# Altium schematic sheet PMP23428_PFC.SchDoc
size 431 x 279 mm; Date: Not shown in title block; ApprovedBy: Not shown in title block; CheckedBy: Not shown in title block; Author: Not shown in title block; CompanyName: Not shown in title block; Engineer: Not shown in title block; Organization: Not shown in title block; Address1: Not shown in title block; Address2: Not shown in title block; Address3: Not shown in title block; Address4: Not shown in title block; DocumentNumber: 1; Revision: Use project parameter SCH_Rev; SheetNumber: 1; SheetTotal: 4; PageSetup: Record=PageOptions¦CenterHorizontal=True¦CenterVertical=True¦PrintScale=1.00¦XCorrection=1.00¦YCorrection=1.00¦PrintKind=0¦BorderSize=5000000¦LeftOffset=0¦BottomOffset=0¦Orientation=2¦PaperLength=1000¦PaperWidth=1000¦Scale=100¦PaperSource=15¦PrintQuality=600¦MediaType=1¦DitherType=10¦PaperKind=Letter¦PrintScaleMode=1
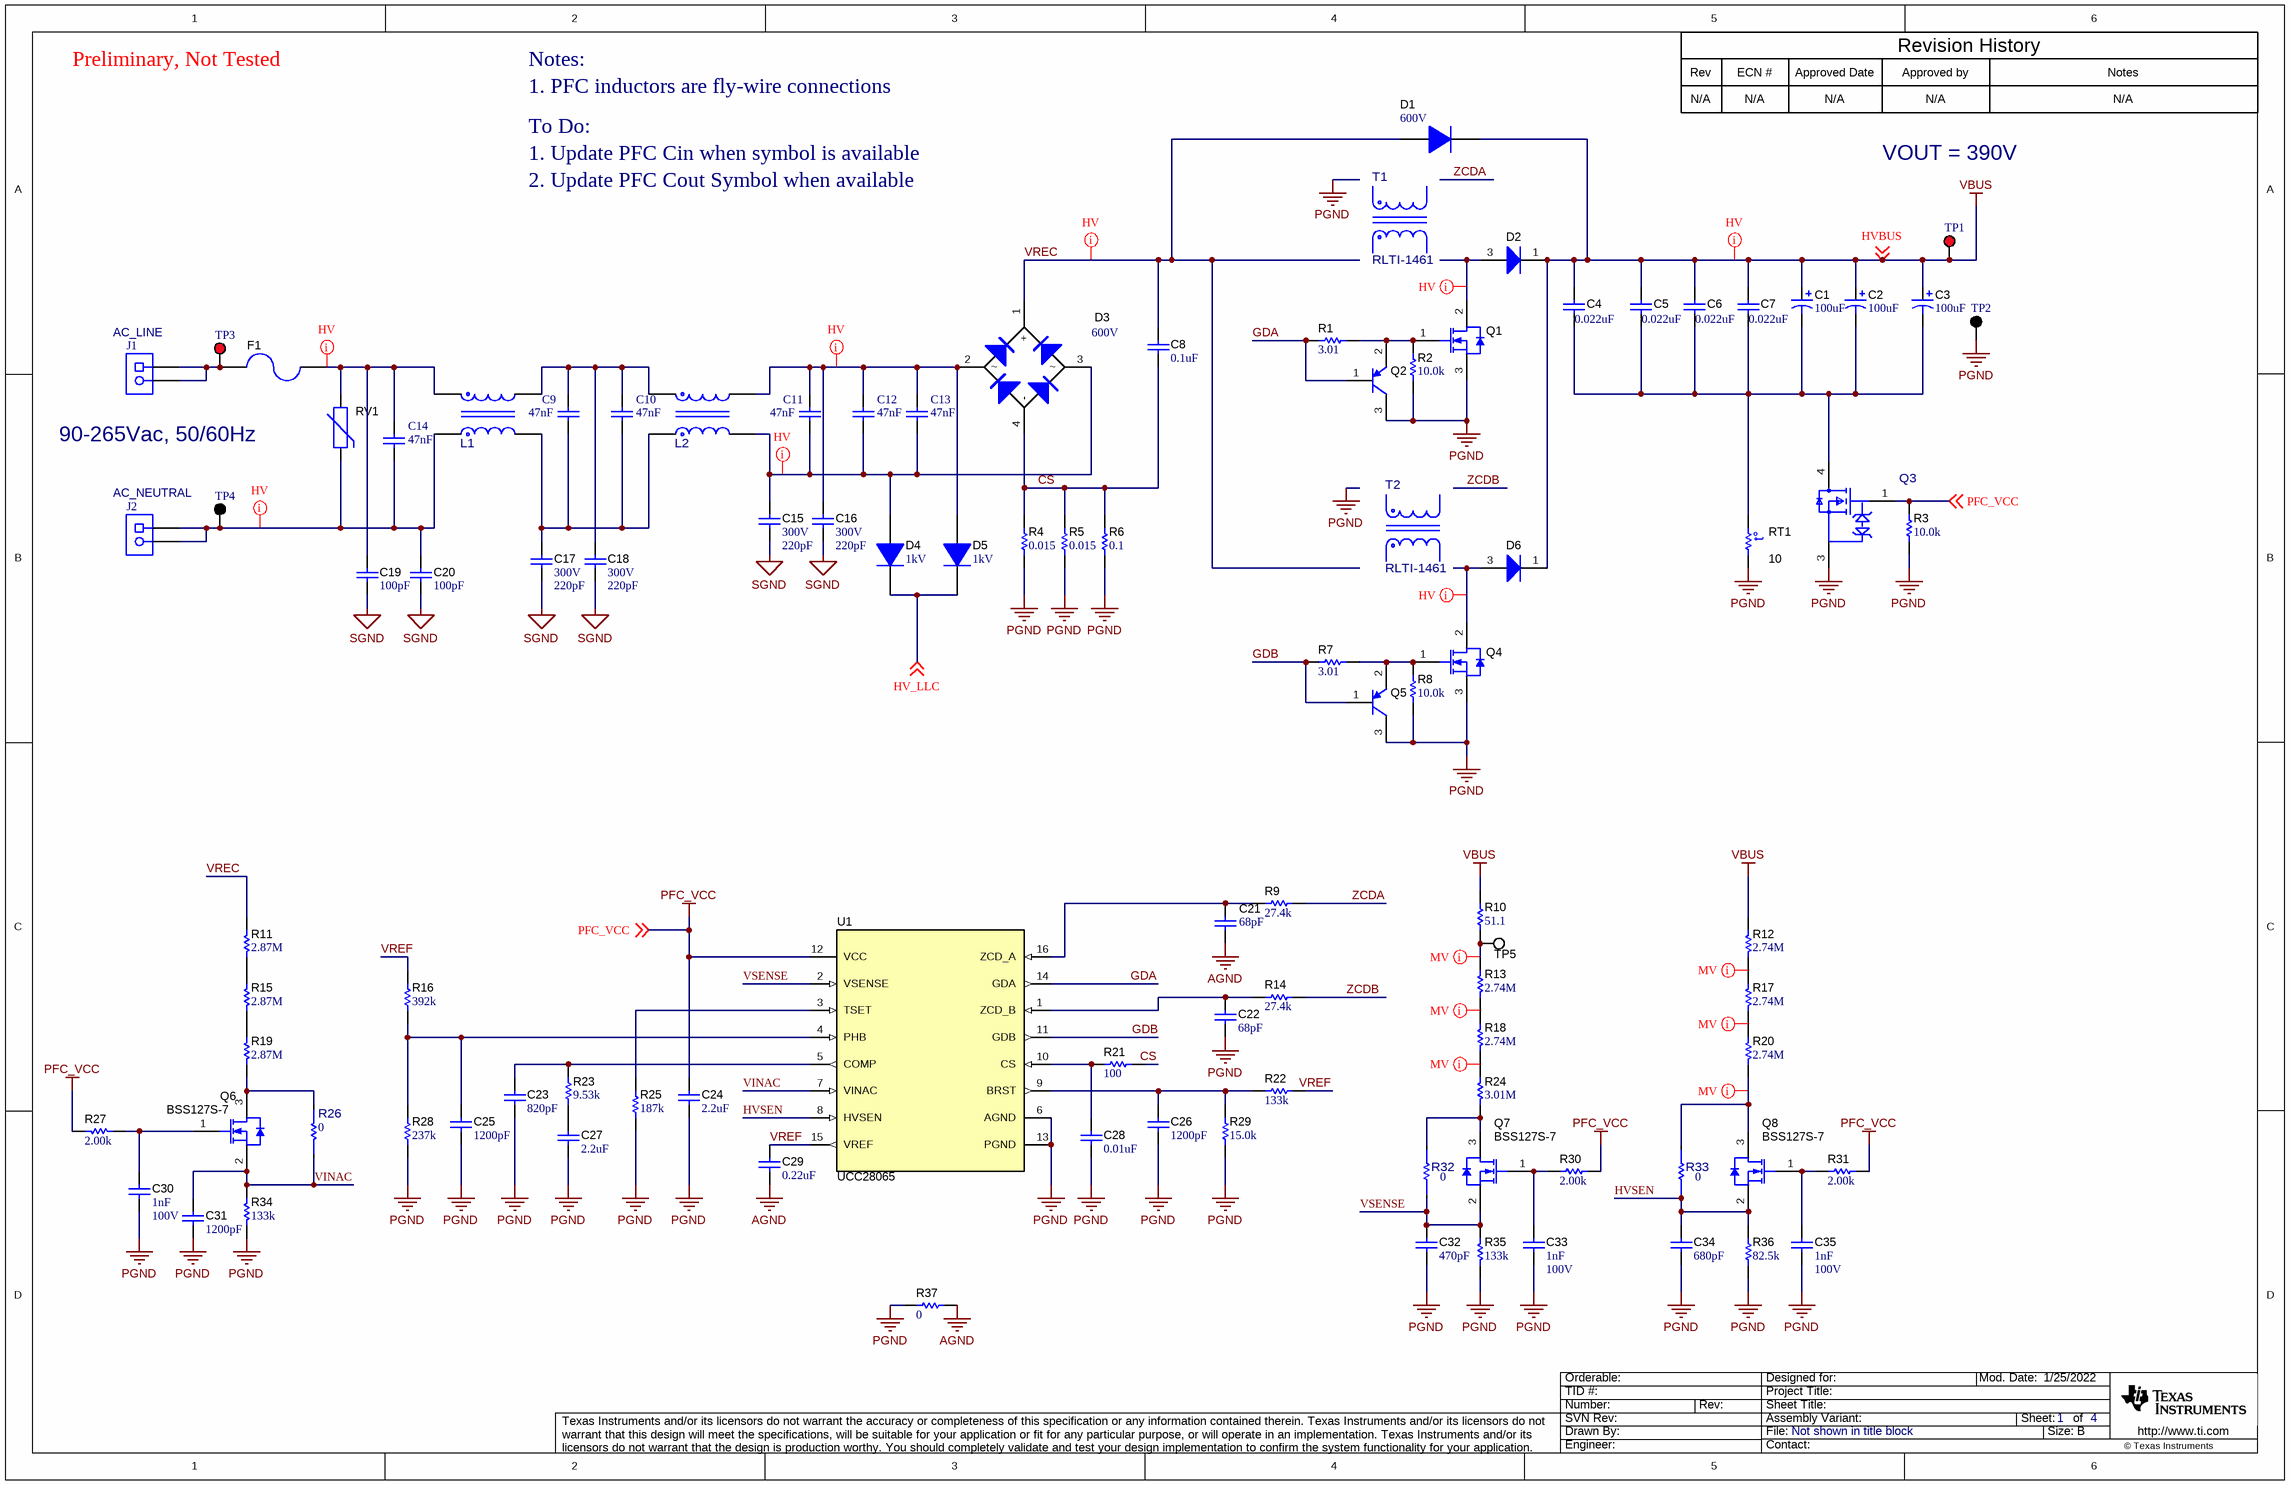
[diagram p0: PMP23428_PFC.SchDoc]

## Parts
C1  ValueDisplayed: 100uF  [KXG_1800x4000_horizontalUp]  (hidden comment: Cap_Polarized)
C2  ValueDisplayed: 100uF  [KXG_1800x4000_horizontalUp]  (hidden comment: Cap_Polarized)
C3  ValueDisplayed: 100uF  [KXG_1800x4000_horizontalDown]  (hidden comment: Cap_Polarized)
C4  ValueDisplayed: 0.022uF  [1210_150]  (hidden comment: GRM32QR72J223KW01L)
C5  ValueDisplayed: 0.022uF  [1210_150]  (hidden comment: GRM32QR72J223KW01L)
C6  ValueDisplayed: 0.022uF  [1210_150]  (hidden comment: GRM32QR72J223KW01L)
C7  ValueDisplayed: 0.022uF  [1210_150]  (hidden comment: GRM32QR72J223KW01L)
C8  ValueDisplayed: 0.1uF  [CAPRR1500W60L1750T550H1250]  (hidden comment: Capacitor)
C9  Cap_F: 47nF  [WCAP-FTX2_L13W4.5H9.5]  (hidden comment: 890324023015)
C10  Cap_F: 47nF  [WCAP-FTX2_L13W4.5H9.5]  (hidden comment: 890324023015)
C11  Cap_F: 47nF  [WCAP-FTX2_L13W4.5H9.5]  (hidden comment: 890324023015)
C12  Cap_F: 47nF  [WCAP-FTX2_L13W4.5H9.5]  (hidden comment: 890324023015)
C13  Cap_F: 47nF  [WCAP-FTX2_L13W4.5H9.5]  (hidden comment: 890324023015)
C14  Cap_F: 47nF  [WCAP-FTX2_L13W4.5H9.5]  (hidden comment: 890324023015)
C15  VDC_V: 300V  ValueDisplayed: 220pF  [B_800x700x800]  (hidden comment: DE6B3KJ221KN3A)
C16  VDC_V: 300V  ValueDisplayed: 220pF  [B_800x700x800]  (hidden comment: DE6B3KJ221KN3A)
C17  VDC_V: 300V  ValueDisplayed: 220pF  [B_800x700x800]  (hidden comment: DE6B3KJ221KN3A)
C18  VDC_V: 300V  ValueDisplayed: 220pF  [B_800x700x800]  (hidden comment: DE6B3KJ221KN3A)
C19  ValueDisplayed: 100pF  [KY_700x500x1000]  (hidden comment: DE2B3KY101KN3AU02F)
C20  ValueDisplayed: 100pF  [KY_700x500x1000]  (hidden comment: DE2B3KY101KN3AU02F)
C21  ValueDisplayed: 68pF  [0805_HV]  (hidden comment: Capacitor)
C22  ValueDisplayed: 68pF  [0805_HV]  (hidden comment: Capacitor)
C23  ValueDisplayed: 820pF  [0805_HV]  (hidden comment: Capacitor)
C24  ValueDisplayed: 2.2uF  [0805_HV]  (hidden comment: Capacitor)
C25  ValueDisplayed: 1200pF  [0805_HV]  (hidden comment: Capacitor)
C26  ValueDisplayed: 1200pF  [0805_HV]  (hidden comment: Capacitor)
C27  ValueDisplayed: 2.2uF  [0805_HV]  (hidden comment: Capacitor)
C28  ValueDisplayed: 0.01uF  [0805_HV]  (hidden comment: Capacitor)
C29  ValueDisplayed: 0.22uF  [1206]  (hidden comment: Capacitor)
C30  Cap_F: 1nF  VDC_V: 100V  [0603]  (hidden comment: C1608X7R2A102K080AA)
C31  ValueDisplayed: 1200pF  [0805_HV]  (hidden comment: Capacitor)
C32  ValueDisplayed: 470pF  [0805_HV]  (hidden comment: Capacitor)
C33  Cap_F: 1nF  VDC_V: 100V  [0603]  (hidden comment: C1608X7R2A102K080AA)
C34  ValueDisplayed: 680pF  [0805_HV]  (hidden comment: Capacitor)
C35  Cap_F: 1nF  VDC_V: 100V  [0603]  (hidden comment: C1608X7R2A102K080AA)
D1  Vr_V: 600V  [SMC]  (hidden comment: DIODE)
D2  MUR860G  [TO-220AC_HORIZ]  (value not drawn)
D3  Vr_V: 600V  [GBU_Horizontal_Down_Standoff2300]  (hidden comment: GBU6J)
D4  Vr_V: 1kV  [DO-41]  (hidden comment: 1N4007-E3/73)
D5  Vr_V: 1kV  [DO-41]  (hidden comment: 1N4007-E3/73)
D6  MUR860G  [TO-220AC_HORIZ]  (value not drawn)
F1  0216008.MXEP  [FUSE_0216]  (value not drawn)
J1  Receptacle_2x1  [On-Shore_ED120_2DS]  (value not drawn)
J2  Receptacle_2x1  [On-Shore_ED120_2DS]  (value not drawn)
L1  7448680120  [FP-7448680120_PTH_CMC_27MM5_25MM0-MFG]  (value not drawn)
L2  7448680120  [FP-7448680120_PTH_CMC_27MM5_25MM0-MFG]  (value not drawn)
Q1  IPP60R099CPXKSA1  [TO-220AB_Horizontal_100mil_Standoff2300]  (value not drawn)
Q2  FMMT718TA  [SOT-23]  (value not drawn)
Q3  STB18N60DM2  [FP-STB18N60DM2_D2PAK-MFG]  (value not drawn)
Q4  IPP60R099CPXKSA1  [TO-220AB_Horizontal_100mil_Standoff2300]  (value not drawn)
Q5  FMMT718TA  [SOT-23]  (value not drawn)
Q6  BSS127S-7  [SOT-23]
Q7  BSS127S-7  [SOT-23]
Q8  BSS127S-7  [SOT-23]
R1  ValueDisplayed: 3.01  [0603]  (hidden comment: RC0603FR-073R01L)
R2  ValueDisplayed: 10.0k  [0805_HV]  (hidden comment: Resistor)
R3  ValueDisplayed: 10.0k  [0805_HV]  (hidden comment: Resistor)
R4  ValueDisplayed: 0.015  [2010]  (hidden comment: Resistor)
R5  ValueDisplayed: 0.015  [2010]  (hidden comment: Resistor)
R6  ValueDisplayed: 0.1  [2010]  (hidden comment: CRM2010-FX-R100ELF)
R7  ValueDisplayed: 3.01  [0603]  (hidden comment: RC0603FR-073R01L)
R8  ValueDisplayed: 10.0k  [0805_HV]  (hidden comment: Resistor)
R9  ValueDisplayed: 27.4k  [0603]  (hidden comment: RC0603FR-0727K4L)
R10  ValueDisplayed: 51.1  [0805_HV]  (hidden comment: Resistor)
R11  ValueDisplayed: 2.87M  [0805_HV]  (hidden comment: Resistor)
R12  ValueDisplayed: 2.74M  [0805_HV]  (hidden comment: Resistor)
R13  ValueDisplayed: 2.74M  [0805_HV]  (hidden comment: Resistor)
R14  ValueDisplayed: 27.4k  [0603]  (hidden comment: RC0603FR-0727K4L)
R15  ValueDisplayed: 2.87M  [0805_HV]  (hidden comment: Resistor)
R16  ValueDisplayed: 392k  [0603]  (hidden comment: RC0603FR-07392KL)
R17  ValueDisplayed: 2.74M  [0805_HV]  (hidden comment: Resistor)
R18  ValueDisplayed: 2.74M  [0805_HV]  (hidden comment: Resistor)
R19  ValueDisplayed: 2.87M  [0805_HV]  (hidden comment: Resistor)
R20  ValueDisplayed: 2.74M  [0805_HV]  (hidden comment: Resistor)
R21  ValueDisplayed: 100  [0805_HV]  (hidden comment: Resistor)
R22  ValueDisplayed: 133k  [0805_HV]  (hidden comment: CRCW0805133KFKEA)
R23  ValueDisplayed: 9.53k  [0805_HV]  (hidden comment: Resistor)
R24  ValueDisplayed: 3.01M  [0805_HV]  (hidden comment: Resistor)
R25  ValueDisplayed: 187k  [0603]  (hidden comment: CRCW0603187KFKEA)
R26  value 0  [FP-RMCF1206ZT0R00_1206-MFG]  (hidden comment: RMCF1206ZT0R00)
R27  ValueDisplayed: 2.00k  [0603]  (hidden comment: RC0603FR-072KL)
R28  ValueDisplayed: 237k  [0603]  (hidden comment: RC0603FR-07237KL)
R29  ValueDisplayed: 15.0k  [0805_HV]  (hidden comment: CRCW080515K0FKEA)
R30  ValueDisplayed: 2.00k  [0603]  (hidden comment: RC0603FR-072KL)
R31  ValueDisplayed: 2.00k  [0603]  (hidden comment: RC0603FR-072KL)
R32  value 0  [FP-RMCF1206ZT0R00_1206-MFG]  (hidden comment: RMCF1206ZT0R00)
R33  value 0  [FP-RMCF1206ZT0R00_1206-MFG]  (hidden comment: RMCF1206ZT0R00)
R34  ValueDisplayed: 133k  [0805_HV]  (hidden comment: CRCW0805133KFKEA)
R35  ValueDisplayed: 133k  [0805_HV]  (hidden comment: Resistor)
R36  ValueDisplayed: 82.5k  [0805_HV]  (hidden comment: Resistor)
R37  ValueDisplayed: 0  [2512]  (hidden comment: Resistor)
RT1  value 10  [S153]  (hidden comment: B57153S0100M000)
RV1  Varistor_MetalOxide  [VAR_S10K275E2]  (value not drawn)
T1  RLTI-1461  [FP-RLTI-1461_PFC_IND_1IN25_3IN0-MFG]
T2  RLTI-1461  [FP-RLTI-1461_PFC_IND_1IN25_3IN0-MFG]
TP1  5010  [Keystone5010]  (value not drawn)
TP2  5011  [Keystone5011]  (value not drawn)
TP3  5010  [Keystone5010]  (value not drawn)
TP4  5011  [Keystone5011]  (value not drawn)
TP5  5002  [Keystone5002]  (value not drawn)
U1  UCC28065  [D0016A_N]

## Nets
AGND: C21.2 C29.2 R37.1
PFC_VCC: C24.2 Q3.1(G) R3.2 R27.2 R30.2 R31.2 U1.12(VCC) ; off-sheet PFC_VCC
PGND: C22.1 C23.1 C24.1 C25.2 C26.2 C27.2 C28.2 C30.2 C31.1 C32.2 C33.2 C34.2 C35.2 Q1.3(S) Q2.3(C) Q3.3(S) Q4.3(S) Q5.3(C) R2.1 R3.1 R4.1 R5.1 R6.1 R8.1 R25.1 R28.1 R29.1 R34.1 R35.1 R36.1 R37.2 RT1.1 TP2.1 U1.6(AGND) U1.13(PGND)
SGND: C15.2 C16.2 C17.2 C18.2 C19.2 C20.2
VBUS: C1.1(+) C2.1(+) C3.1(+) C4.1 C5.1 C6.1 C7.1 D1.1(K) D2.1(K) D6.1(K) R10.2 R12.2 TP1.1 ; off-sheet HVBUS  [also labelled HVBUS]
CS: C8.2 D3.4(-) R4.2 R5.2 R6.2 R21.2
GDA: Q2.1(B) R1.1 U1.14(GDA)
GDB: Q5.1(B) R7.1 U1.11(GDB)
HV_LLC: D4.1(K) D5.1(K) ; off-sheet HV_LLC
HVSEN: C34.1 Q8.2(S) R33.1 R36.2 U1.8(HVSEN)
VINAC: C31.2 Q6.2(S) R26.1 R34.2 U1.7(VINAC)
VREC: C8.1 D1.2(A) D3.1(+) R11.1
VREF: C29.1 R16.2 R22.2 U1.15(VREF)
VSENSE: C32.1 Q7.2(S) R32.1 R35.2 U1.2(VSENSE)
ZCDA: R9.2
ZCDB: R14.2
NetC1_2: C1.2(-) C2.2(-) C3.2(-) C4.2 C5.2 C6.2 C7.2 Q3.4(D) RT1.2
NetC9_1: C9.1 C10.1 C17.1 L1.2 L2.1
NetC9_2: C9.2 C10.2 C18.1 L1.3 L2.4
NetC11_1: C11.1 C12.1 C13.1 C15.1 D3.3 D4.2(A) L2.2
NetC11_2: C11.2 C12.2 C13.2 C16.1 D3.2 D5.2(A) L2.3
NetC14_1: C14.1 C20.1 J2.1 J2.2 L1.1 RV1.2 TP4.1
NetC14_2: C14.2 C19.1 F1.1 L1.4 RV1.1
NetC21_1: C21.1 R9.1 U1.16(ZCD_A)
NetC22_2: C22.2 R14.1 U1.1(ZCD_B)
NetC23_2: C23.2 R23.2 U1.5(COMP)
NetC25_1: C25.1 R16.1 R28.2 U1.4(PHB)
NetC26_1: C26.1 R22.1 R29.2 U1.9(BRST)
NetC27_1: C27.1 R23.1
NetC28_1: C28.1 R21.1 U1.10(CS)
NetC30_1: C30.1 Q6.1(G) R27.1
NetC33_1: C33.1 Q7.1(G) R30.1
NetC35_1: C35.1 Q8.1(G) R31.1
NetD2_3: D2.3(A) Q1.2(D)
NetD6_3: D6.3(A) Q4.2(D)
NetF1_2: F1.2 J1.1 J1.2 TP3.1
NetQ1_1: Q1.1(G) Q2.2(E) R1.2 R2.2
NetQ4_1: Q4.1(G) Q5.2(E) R7.2 R8.2
NetQ6_3: Q6.3(D) R19.1 R26.2
NetQ7_3: Q7.3(D) R24.2 R32.2
NetQ8_3: Q8.3(D) R20.1 R33.2
NetR10_1: R10.1 R13.1 TP5.1
NetR11_2: R11.2 R15.1
NetR12_1: R12.1 R17.2
NetR13_2: R13.2 R18.1
NetR15_2: R15.2 R19.2
NetR17_1: R17.1 R20.2
NetR18_2: R18.2 R24.1
NetR25_2: R25.2 U1.3(TSET)

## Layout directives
net class HV: NetC11_1, NetC11_2, NetC14_1, NetC14_2, NetD2_3, NetD6_3, VBUS, VREC
net class MV: NetQ8_3, NetR10_1, NetR12_1, NetR13_2, NetR17_1, NetR18_2

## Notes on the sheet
- Preliminary, Not Tested
- Notes:
- 1. PFC inductors are fly-wire connections
- Rev
- N/A
- ECN #
- Approved Date
- Approved by
- Revision History
- Notes
- To Do:
- 1. Update PFC Cin when symbol is available
- VOUT = 390V
- 2. Update PFC Cout Symbol when available
- (near J1) AC_LINE
- 90-265Vac, 50/60Hz
- (near J2) AC_NEUTRAL

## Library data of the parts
C1-C3 = CMP-0010042-2: CAP, AL, 100 uF, 450 V, +/- 20%, TH; PartNumber: EKXG451ELL101MM40S; Manufacturer: Chemi-Con; Polarized: Y; CompType: Capacitor; Value: 100uF; U/M: EA; Cap_F: 100µF; Value1: Unknown; VDC_V: 450V; IRMS_A: 8dA; TaMin_C: -25°C; TaMax_C: 105°C; Cap_Case: 18x40mm; SizeAreaWB_mm2: 400; SizeArea_mm2: 324; SizeX_mm: 18; SizeZ_mm: 41.5; AEC Category: Q200; AEC Qualified: N
C4-C7 = CMP-0009248-2: CAP, CERM, 0.022 uF, 630 V, +/- 10%, X7R, 1210; Manufacturer: MuRata; TaMin_C: -55°C; Polarized: N; SizeAreaWB_mm2: 14.7; Value1: Unknown; U/M: EA; TaMax_C: 125°C; SizeZ_mm: 1.5; SizeX_mm: 3.2; SizeY_mm: 2.5; Cap_Case: 1210; Value2: 630V; SizeArea_mm2: 8; Cap_F: 22nF; AEC Category: Q200
C8 = CMP-0012496-3: CAP, Film, 0.1 uF, 275 V, +/- 20%, TH; PartNumber: ECQ-U2A104ML; Manufacturer: Panasonic; Polarized: N; Value: 0.1uF; Cap_F: 100nF; Value1: Unknown; VDC_V: 275V; TaMin_C: -40°C; TaMax_C: 100°C; Cap_Case: Radial 17.5x5.5x12.5; AEC Category: Q200
C9-C14 = CMP-0112456-1: WCAP-FTX2 Film Capacitor, THT, L13 x W4.5 x H9.5mm, 47nF, 275V; Manufacturer: Wurth Elektronik; Capacitance Tolerance: +/-10%; Dissipation Factor @100kHz: 0.5%; Dissipation Factor @10kHz: 0.1%; Insulation Resistance: 30000MOhm; Pitch: 10mm; Rate of Voltage Rise: 300V/us; Technical Reference: MX2P010473K275ASPB15000
C15-C18 = CMP-0009612-2: CAP, CERM, 220 pF, 300 V, +/- 10%, B, TH, 2- Leads, Body 8x7mm, Pin Spacing 7.5mm; Manufacturer: MuRata; TaMin_C: -40°C; Polarized: N; SizeAreaWB_mm2: 90; Value1: Unknown; U/M: EA; Value: 220pF; TaMax_C: 125°C; SizeZ_mm: 11; SizeX_mm: 8; SizeY_mm: 7; Cap_Case: 8x7x8mm; SizeArea_mm2: 56; AEC Category: Q200
C19 C20 = CMP-0009606-4: CAP, CERM, 100 pF, X1 250 VAC/Y2 300 VAC, +/- 10%, B, TH; Manufacturer: MuRata; TaMin_C: -25°C; Polarized: N; SizeAreaWB_mm2: 66.5; Value1: Unknown; U/M: EA; Value: 100pF; TaMax_C: 85°C; SizeZ_mm: 10; SizeX_mm: 7.5; SizeY_mm: 5; Cap_Case: 7x5x10mm; SizeArea_mm2: 37.5; AEC Category: Q200; AC_Safety: X1Y2; VAC_X: 250V; VAC_Y: 300V
C21 C22 = CMP-0007622-2: CAP, CERM, 68 pF, 50 V, +/- 5%, C0G/NP0, 0805; PartNumber: 08055A680JAT2A; Manufacturer: AVX; Polarized: N; Value: 68pF; U/M: EA; ESR_ohm: 4.5d; Value1: 0.45 ohm; VDC_V: 50V; TaMin_C: -55°C; TaMax_C: 125°C; Cap_Case: 0805; SizeArea_mm2: 2.5; SizeAreaWB_mm2: 6.75; SizeX_mm: 2; SizeY_mm: 1.25; SizeZ_mm: 1.45; AEC Category: Q200
C23 = CMP-0008153-2: CAP, CERM, 820 pF, 25 V, +/- 10%, X7R, 0805; PartNumber: GRM216R71E821KA01D; Manufacturer: MuRata; Polarized: N; Value: 820pF; U/M: EA; Value1: Unknown; VDC_V: 25V; TaMin_C: -55°C; TaMax_C: 125°C; Cap_Case: 0805; SizeArea_mm2: 2.5; SizeAreaWB_mm2: 6.75; SizeX_mm: 2; SizeY_mm: 1.25; SizeZ_mm: 1.45; AEC Category: Q200
C24 C27 = CMP-0007877-2: CAP, CERM, 2.2 uF, 50 V, +/- 10%, X7R, 0805; PartNumber: C2012X7R1H225K125AC; Manufacturer: TDK; Polarized: N; Value: 2.2uF; U/M: EA; Cap_F: 2.2µF; ESR_ohm: 3.66m; Value1: 0.00366 ohm; VDC_V: 50V; IRMS_A: 3.41207A; TaMin_C: -55°C; TaMax_C: 125°C; Cap_Case: 0805; SizeArea_mm2: 2.5; SizeAreaWB_mm2: 6.75; SizeX_mm: 2; SizeY_mm: 1.25; SizeZ_mm: 1.45; AEC Category: Q200
C25 C26 C31 = CMP-0008142-2: CAP, CERM, 1200 pF, 25 V, +/- 10%, X7R, 0805; PartNumber: GRM216R71E122KA01D; Manufacturer: MuRata; Polarized: N; Value: 1200pF; U/M: EA; Cap_F: 1.2nF; Value1: Unknown; VDC_V: 25V; TaMin_C: -55°C; TaMax_C: 125°C; Cap_Case: 0805; SizeArea_mm2: 2.5; SizeAreaWB_mm2: 6.75; SizeX_mm: 2; SizeY_mm: 1.25; SizeZ_mm: 1.45; AEC Category: Q200
C28 = CMP-0007629-2: CAP, CERM, 0.01 uF, 50 V, +/- 5%, X7R, 0805; PartNumber: 08055C103JAT2A; Manufacturer: AVX; Polarized: N; Value: 0.01uF; U/M: EA; Cap_F: 10nF; ESR_ohm: 0.078; Value1: 0.078 ohm; VDC_V: 50V; TaMin_C: -55°C; TaMax_C: 125°C; Cap_Case: 0805; SizeArea_mm2: 2.5; SizeAreaWB_mm2: 6.75; SizeX_mm: 2; SizeY_mm: 1.25; SizeZ_mm: 1.45; AEC Category: Q200
C29 = CMP-0008995-2: CAP, CERM, 0.22 uF, 50 V, +/- 10%, X7R, 1206; PartNumber: GRM31MR71H224KA01L; Manufacturer: MuRata; Polarized: N; Value: 0.22uF; U/M: EA; Cap_F: 220nF; Value1: Unknown; VDC_V: 50V; TaMin_C: -55°C; TaMax_C: 125°C; SizeArea_mm2: 5.12; SizeAreaWB_mm2: 10.92; SizeX_mm: 3.2; SizeY_mm: 1.6; SizeZ_mm: 1.35; AEC Category: Q200
C30 C33 C35 = CMP-0007053-4: CAP, CERM, 1000 pF, 100 V, +/- 10%, X7R, 0603; Manufacturer: TDK; TaMin_C: -55°C; Polarized: N; SizeAreaWB_mm2: 4.68; Value1: Unknown; U/M: EA; Value: 1000pF; TaMax_C: 125°C; SizeZ_mm: 1; SizeX_mm: 1.6; SizeY_mm: 0.8; SizeArea_mm2: 1.28; AEC Category: Q200
C32 = CMP-0008150-2: CAP, CERM, 470 pF, 25 V, +/- 10%, X7R, 0805; PartNumber: GRM216R71E471KA01D; Manufacturer: MuRata; Polarized: N; Value: 470pF; U/M: EA; Value1: Unknown; VDC_V: 25V; TaMin_C: -55°C; TaMax_C: 125°C; Cap_Case: 0805; SizeArea_mm2: 2.5; SizeAreaWB_mm2: 6.75; SizeX_mm: 2; SizeY_mm: 1.25; SizeZ_mm: 1.45; AEC Category: Q200
C34 = CMP-0007693-2: CAP, CERM, 680 pF, 25 V, +/- 10%, X7R, 0805; PartNumber: 885012207059; Manufacturer: Wurth Elektronik; Polarized: N; Value: 680pF; U/M: EA; Value1: Unknown; VDC_V: 25V; TaMin_C: -55°C; TaMax_C: 125°C; Cap_Case: 0805; SizeArea_mm2: 2.5; SizeAreaWB_mm2: 6.75; SizeX_mm: 2; SizeY_mm: 1.25; SizeZ_mm: 1.45; AEC Category: Q200
D1 = CMP-0076905-1: Diode, Ultrafast, 600 V, 3 A, SMC; PartNumber: MURS360T3G; Manufacturer: ON Semiconductor; U/M: EA; Vf_V: 1.25V; Value: 600V; Value1: 3A; TJmax_C: 175°C; RJC_CperW: 11.0; SizeAreaWB_mm2: 83.2686; SizeArea_mm2: 50.5686; SizeX_mm: 8.13; SizeY_mm: 6.22; SizeZ_mm: 2.6; AEC Category: Q101; Green_Lifecycle: Active; Green_REACh: Passed
D2 D6 = CMP-0029037-2: Diode, Ultrafast, 600 V, 8 A, TH; Manufacturer: ON Semiconductor; TJmax_C: 175°C; Green_Lifecycle: Not Set; SizeX_mm: 10.15; SizeAreaWB_mm2: 78.975; RJC_CperW: 4.75; SizeArea_mm2: 45.675; Green_REACh: Incomplete; Vf_V: 980mV; Value2: 0.98V; Io_A: 8A; SizeY_mm: 4.5; AEC Category: Q101; SizeZ_mm: 23; Value: 600V
D3 = CMP-0029269-2: Diode, Switching-Bridge, 600 V, 6 A, TH; Manufacturer: Fairchild Semiconductor; U/M: EA; Vf_V: 1V; Value: 600V; Value1: 6A; TJmax_C: 150°C; RJC_CperW: 3.1; SizeAreaWB_mm2: 130.5915; SizeArea_mm2: 75.6315; SizeX_mm: 22.05; SizeY_mm: 3.43; SizeZ_mm: 21.55; AEC Category: Q101; AEC Qualified: N; Green_Lifecycle: Active; Green_REACh: Passed
D4 D5 = CMP-0029188-2: Diode, P-N, 1000 V, 1 A, TH; Manufacturer: Vishay-Semiconductor; Io_A: 1A; SizeAreaWB_mm2: 43.424; TJmax_C: 150°C; Value: 1000V; SizeZ_mm: 23.4; SizeX_mm: 7.2; SizeY_mm: 2.72; Vf_V: 1.1V; SizeArea_mm2: 19.584; AEC Qualified: N; AEC Category: Q101
F1 = CMP-0079917-1: Fuse, 8 A, 250 VAC, TH; Manufacturer: Littelfuse; VAC_V: 250V; Rtyp_Ohm: 0.0123; MeltingTyp: 64.315; Irating_A: 8A; Interrupt_AC: 1.5kA
J1 J2 = CMP-0074910-1: Terminal Block, 5.08 mm, 2x1, Brass, TH; PartNumber: ED120/2DS; Manufacturer: On-Shore Technology; Pitch_mm: 5.08; Gender: Female; Shrouded: N; Row_Count: 1; Current_A: 15A; Voltage_V: 300V; Cert_CULUS: Y; Green_Lifecycle: Not Set; Green_REACh: Incomplete; CNHeader: False; CT: True
L1 L2 = CMP-0120034-1: 330 µH @ 10 kHz 2 Line Common Mode Choke Through Hole 12A DCR 6mOhm; Manufacturer: Wurth Electronics; DCR_ohm: 6m; Ind_H: 330µH; SizeZ_mm: 10mm; AEC Qualified: No; TaMax_C: +60°C; TaMin_C: -40°C; Test Frequency: 10kHz; Tolerance_%: 40%
Q1 Q4 = CMP-0001172-3: MOSFET, N-CH, 600 V, 31 A, TO-220AB; Alternate Manufacturer: None; Manufacturer: Infineon Technologies; SizeZ_mm: 19.4; ChType: N; Value2: 60 nC; VdsMax_V: 600V; SizeX_mm: 10.2; SizeY_mm: 4.5; Vgs_V: 20V; Value: 600V; SizeArea_mm2: 45.9; AEC Category: Q101; IdsMax_A: 31A; SizeAreaWB_mm2: 79.3; U/M: EA; QgTyp_nC: 60
Q2 Q5 = CMP-0000330-2: Transistor, PNP, 20 V, 1.5 A, SOT-23; Manufacturer: Diodes Inc.; TaMax_C: 150°C; Value2: 6; Value1: 1.5 A; Vcesat1_V: 20V; SizeX_mm: 2.5; SizeY_mm: 3; TaMin_C: -55°C; IcRated_A: 1.5A; CompType: BJT; SizeZ_mm: 1.1; Value: 20 V; SizeArea_mm2: 7.5; NPN: 0; PNP: 1; AEC Category: Q101; SizeAreaWB_mm2: 14; U/M: EA
Q3 = CMP-0084087-1: N-Channel 600V 12A (Tc) 90W (Tc) Surface Mount D2PAK; Manufacturer: STMicroelectronics; Rdson45_ohm: 0.26Ω; Threshold Vgs Max: 5V; Input Capacitace At Vds: 800pF @ 100V; Turn On Delay Time: 13.5ns; AEC Qualified: No; ChMode: False; Symbol Name: SYM-STB18N60DM2; Max Forward Diode Voltage: 1.6V; Vgs_V: 25V; Pulse Drain Current: 48A; Standoff Height: 0.03mm; Reverse Recovery Time: 125ns; Number Of N Channels: 1; Turn Off Delay Time: 9.5ns; QgTyp_nC: 20nC @ 10V; TJmax_C: +150°C; Reverse Recovery Charge: 675nC; Power_W: 110W; SizeZ_mm: 4.83mm; Threshold Vgs Min: 3V
Q6-Q8 = CMP-0001149-3: MOSFET, N-CH, 600 V, 0.05 A, SOT-23; Alternate Manufacturer: None; Manufacturer: Diodes Inc.; SizeZ_mm: 1.1; ChType: N; Value2: 1.08 nC; VdsMax_V: 600V; SizeX_mm: 2.5; SizeY_mm: 3; Vgs_V: 20V; QgTyp_nC: 1.08; Value: 600V; SizeArea_mm2: 7.5; AEC Category: Q101; IdsMax_A: 50mA; SizeAreaWB_mm2: 14; U/M: EA
R1 R7 = CMP-0023093-5: RES, 3.01, 1%, 0.1 W, 0603; Manufacturer: Yageo; Power_W: 100mW; TempCo: 200 ppm/C; Value_Code: 3R01; Value: 3.01; EIA_Code: E96; SizeX_mm: 1.6; SizeY_mm: 0.8; SizeZ_mm: 1; Value2: 0.1W; SizeArea_mm2: 1.28; AEC Qualified: N; VDC_V: 75V; AEC Category: Q200; SizeAreaWB_mm2: 4.68
R2 R3 R8 = CMP-0020842-3: RES, 10.0 k, 1%, 0.125 W, AEC-Q200 Grade 0, 0805; PartNumber: CRCW080510K0FKEA; Manufacturer: Vishay-Dale; Value: 10.0k; Res_ohm: 10k; Value_Code: 10k0; Power_W: 125mW; Value2: 0.125W; VDC_V: 150V; TempCo: 100 ppm/C; SizeArea_mm2: 2.5; SizeX_mm: 2; SizeY_mm: 1.25; SizeZ_mm: 1.45; EIA_Code: E96; AEC Category: Q200; AEC Qualified: Y; AEC Grade: 0
R4 R5 = CMP-0016558-2: RES, 0.015, 1%, 0.5 W, 2010; PartNumber: WSL2010R0150FEA; Manufacturer: Vishay-Dale; Value: 0.015; Value_Code: R015; Power_W: 500mW; Value2: 0.5W; TempCo: 75 ppm/C; SizeArea_mm2: 12.5; SizeX_mm: 5; SizeY_mm: 2.5; SizeZ_mm: 1.66; EIA_Code: E96; U/M: EA; AEC Category: Q200
R6 = CMP-0016505-2: RES, 0.1, 1%, 1 W, 2010; Manufacturer: Bourns; Power_W: 1W; TempCo: 150 ppm/C; Value_Code: R100; U/M: EA; Value: 0.1; EIA_Code: E96; Res_ohm: 1d; SizeX_mm: 5; SizeY_mm: 2.5; SizeZ_mm: 1.66; SizeArea_mm2: 12.5; VDC_V: 0V; AEC Category: Q200
R9 R14 = CMP-0022965-5: RES, 27.4 k, 1%, 0.1 W, 0603; Manufacturer: Yageo; Power_W: 100mW; TempCo: 100 ppm/C; Value_Code: 27k4; Value: 27.4k; EIA_Code: E96; SizeX_mm: 1.6; SizeY_mm: 0.8; SizeZ_mm: 1; Value2: 0.1W; SizeArea_mm2: 1.28; AEC Qualified: N; VDC_V: 75V; AEC Category: Q200; SizeAreaWB_mm2: 4.68
R10 = CMP-0020156-2: RES, 51.1, 0.1%, 0.125 W, 0805; PartNumber: RT0805BRD0751R1L; Manufacturer: Yageo America; Value: 51.1; Value_Code: 51R1; Power_W: 125mW; Value2: 0.125W; VDC_V: 150V; TempCo: 25 ppm/C; SizeArea_mm2: 2.5; SizeX_mm: 2; SizeY_mm: 1.25; SizeZ_mm: 1.45; EIA_Code: E192; U/M: EA; AEC Category: Q200
R11 R15 R19 = CMP-0021139-3: RES, 2.87 M, 1%, 0.125 W, AEC-Q200 Grade 0, 0805; PartNumber: CRCW08052M87FKEA; Manufacturer: Vishay-Dale; Value: 2.87Meg; Value_Code: 2M87; Power_W: 125mW; Value2: 0.125W; VDC_V: 150V; TempCo: 100 ppm/C; SizeArea_mm2: 2.5; SizeX_mm: 2; SizeY_mm: 1.25; SizeZ_mm: 1.45; EIA_Code: E96; AEC Category: Q200; AEC Qualified: Y; AEC Grade: 0
R12 R13 R17 R18 R20 = CMP-0021137-3: RES, 2.74 M, 1%, 0.125 W, AEC-Q200 Grade 0, 0805; PartNumber: CRCW08052M74FKEA; Manufacturer: Vishay-Dale; Value: 2.74Meg; Value_Code: 2M74; Power_W: 125mW; Value2: 0.125W; VDC_V: 150V; TempCo: 100 ppm/C; SizeArea_mm2: 2.5; SizeX_mm: 2; SizeY_mm: 1.25; SizeZ_mm: 1.45; EIA_Code: E96; AEC Category: Q200; AEC Qualified: Y; AEC Grade: 0
R16 = CMP-0023070-4: RES, 392 k, 1%, 0.1 W, 0603; Manufacturer: Yageo; Power_W: 100mW; TempCo: 100 ppm/C; Value: 392k; EIA_Code: E96; SizeX_mm: 1.6; SizeY_mm: 0.8; SizeZ_mm: 1; Value2: 0.1W; SizeArea_mm2: 1.28; AEC Qualified: N; VDC_V: 75V; AEC Category: Q200; SizeAreaWB_mm2: 4.68
R21 = CMP-0020835-3: RES, 100, 1%, 0.125 W, AEC-Q200 Grade 0, 0805; PartNumber: CRCW0805100RFKEA; Manufacturer: Vishay-Dale; Value: 100; Value_Code: 100R; Power_W: 125mW; Value2: 0.125W; VDC_V: 150V; TempCo: 100 ppm/C; SizeArea_mm2: 2.5; SizeX_mm: 2; SizeY_mm: 1.25; SizeZ_mm: 1.45; EIA_Code: E96; AEC Category: Q200; AEC Qualified: Y; AEC Grade: 0
R22 R34 = CMP-0020881-3: RES, 133 k, 1%, 0.125 W, AEC-Q200 Grade 0, 0805; Manufacturer: Vishay-Dale; Power_W: 125mW; TempCo: 100 ppm/C; Value: 133k; EIA_Code: E96; SizeX_mm: 2; SizeY_mm: 1.25; SizeZ_mm: 1.45; Value2: 0.125W; SizeArea_mm2: 2.5; AEC Qualified: Y; VDC_V: 150V; AEC Category: Q200; AEC Grade: 0
R23 = CMP-0021817-2: RES, 9.53 k, 1%, 0.125 W, 0805; PartNumber: ERJ-6ENF9531V; Manufacturer: Panasonic; Value: 9.53k; Value_Code: 9k53; Power_W: 125mW; Value2: 0.125W; TempCo: 100 ppm/C; SizeArea_mm2: 2.5; SizeX_mm: 2; SizeY_mm: 1.25; SizeZ_mm: 1.45; EIA_Code: E96; U/M: EA; AEC Category: Q200
R24 = CMP-0021219-4: RES, 3.01 M, 1%, 0.125 W, AEC-Q200 Grade 0, 0805; PartNumber: CRCW08053M01FKEA; Manufacturer: Vishay-Dale; Value: 3.01Meg; Value_Code: 3M01; Power_W: 125mW; Value2: 0.125W; VDC_V: 150V; TempCo: 100 ppm/C; SizeArea_mm2: 2.5; SizeX_mm: 2; SizeY_mm: 1.25; SizeZ_mm: 1.45; EIA_Code: E96; AEC Category: Q200; AEC Qualified: Y; AEC Grade: 0
R25 = CMP-0022095-4: RES, 187 k, 1%, 0.1 W, AEC-Q200 Grade 0, 0603; Manufacturer: Vishay-Dale; Power_W: 100mW; TempCo: 100 ppm/C; Value: 187k; EIA_Code: E96; SizeX_mm: 1.6; SizeY_mm: 0.8; SizeZ_mm: 1; Value2: 0.1W; SizeArea_mm2: 1.28; AEC Qualified: Y; VDC_V: 75V; AEC Category: Q200; AEC Grade: 0
R26 R32 R33 = CMP-0093609-1: 0Ω ±0 0.25W 1206 Thick Film Chip Resistor AEC-Q200 compliant; Manufacturer: Stackpole Electronics; AEC Qualified: Yes; VDC_V: 200V; AEC Grade: Grade 0; Power_W: 250mW; SizeZ_mm: 0.7mm
R27 R30 R31 = CMP-0023000-5: RES, 2.00 k, 1%, 0.1 W, 0603; Manufacturer: Yageo; Power_W: 100mW; TempCo: 100 ppm/C; Value_Code: 2k00; Value: 2.00k; EIA_Code: E96; Res_ohm: 2k; SizeX_mm: 1.6; SizeY_mm: 0.8; SizeZ_mm: 1; Value2: 0.1W; SizeArea_mm2: 1.28; AEC Qualified: N; VDC_V: 75V; AEC Category: Q200; SizeAreaWB_mm2: 4.68
R28 = CMP-0022931-4: RES, 237 k, 1%, 0.1 W, 0603; Manufacturer: Yageo; Power_W: 100mW; TempCo: 100 ppm/C; Value: 237k; EIA_Code: E96; SizeX_mm: 1.6; SizeY_mm: 0.8; SizeZ_mm: 1; Value2: 0.1W; SizeArea_mm2: 1.28; AEC Qualified: N; VDC_V: 75V; AEC Category: Q200; SizeAreaWB_mm2: 4.68
R29 = CMP-0020909-3: RES, 15.0 k, 1%, 0.125 W, AEC-Q200 Grade 0, 0805; Manufacturer: Vishay-Dale; Power_W: 125mW; TempCo: 100 ppm/C; Value_Code: 15k0; Value: 15.0k; EIA_Code: E96; Res_ohm: 15k; SizeX_mm: 2; SizeY_mm: 1.25; SizeZ_mm: 1.45; Value2: 0.125W; SizeArea_mm2: 2.5; AEC Qualified: Y; VDC_V: 150V; AEC Category: Q200; AEC Grade: 0
R35 = CMP-0020881-3: RES, 133 k, 1%, 0.125 W, AEC-Q200 Grade 0, 0805; PartNumber: CRCW0805133KFKEA; Manufacturer: Vishay-Dale; Value: 133k; Power_W: 125mW; Value2: 0.125W; VDC_V: 150V; TempCo: 100 ppm/C; SizeArea_mm2: 2.5; SizeX_mm: 2; SizeY_mm: 1.25; SizeZ_mm: 1.45; EIA_Code: E96; AEC Category: Q200; AEC Qualified: Y; AEC Grade: 0
R36 = CMP-0021455-3: RES, 82.5 k, 1%, 0.125 W, AEC-Q200 Grade 0, 0805; PartNumber: CRCW080582K5FKEA; Manufacturer: Vishay-Dale; Value: 82.5k; Value_Code: 82k5; Power_W: 125mW; Value2: 0.125W; VDC_V: 150V; TempCo: 100 ppm/C; SizeArea_mm2: 2.5; SizeX_mm: 2; SizeY_mm: 1.25; SizeZ_mm: 1.45; EIA_Code: E96; AEC Category: Q200; AEC Qualified: Y; AEC Grade: 0
R37 = CMP-0015864-3: RES, 0, 5%, 1 W, AEC-Q200 Grade 0, 2512; PartNumber: CRCW25120000Z0EG; Manufacturer: Vishay-Dale; Value: 0; Value_Code: 0000; Power_W: 1W; TempCo: ppm/C; SizeArea_mm2: 20.16; SizeX_mm: 6.3; SizeY_mm: 3.2; SizeZ_mm: 0.71; EIA_Code: E24; AEC Category: Q200; AEC Qualified: Y
RT1 = CMP-0002550-2: Thermistor NTC, 10 ohm, 20%, 8.5mm Disc; Manufacturer: TDK; TaMax_C: 175°C; TaMin_C: -55°C; Power_W: 1.4W; U/M: EA
RV1 = CMP-0002100-2: Varistor 275V RMS 10MM Radial, TH; PartNumber: S10K275E2; Manufacturer: TDK; SizeAreaWB_mm2: 103.6; SizeArea_mm2: 64.8; SizeX_mm: 12; SizeY_mm: 5.4; SizeZ_mm: 14.5
T1 T2 = CMP-0120250-1: PFCINDUCTOR PMP23428 683W; Manufacturer: Renco Electronics; DCR_ohm: 18m; Ind_H: 85µH; Ns1toNp: 1:0.2; SizeZ_mm: 0.39inch; AEC Qualified: No
TP1 TP3 = CMP-0055147-2: Test Point, Multipurpose, Red, TH; Manufacturer: Keystone Electronics; CT: TRUE; ContactFinish: Silver; Green_Lifecycle: Active; CNHeader: FALSE; Green_REACh: Passed
TP2 TP4 = CMP-0055148-2: Test Point, Multipurpose, Black, TH; Manufacturer: Keystone Electronics; CNHeader: FALSE; ContactFinish: Silver; Green_REACh: Passed; Green_Lifecycle: Active; CT: TRUE
TP5 = CMP-0055139-1: Test Point, Miniature, White, TH; Manufacturer: Keystone; CNHeader: FALSE; Green_Lifecycle: Active; Green_REACh: Passed; ContactFinish: Silver; CT: TRUE
U1 = CMP-0065070-4: Manufacturer: Texas Instruments; SizeX_mm: 6.0; SizeY_mm: 9.9; CompType: IC; SizeZ_mm: 1.75; SizeArea_mm2: 59.4; SizeAreaWB_mm2: 95.2; U/M: EA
